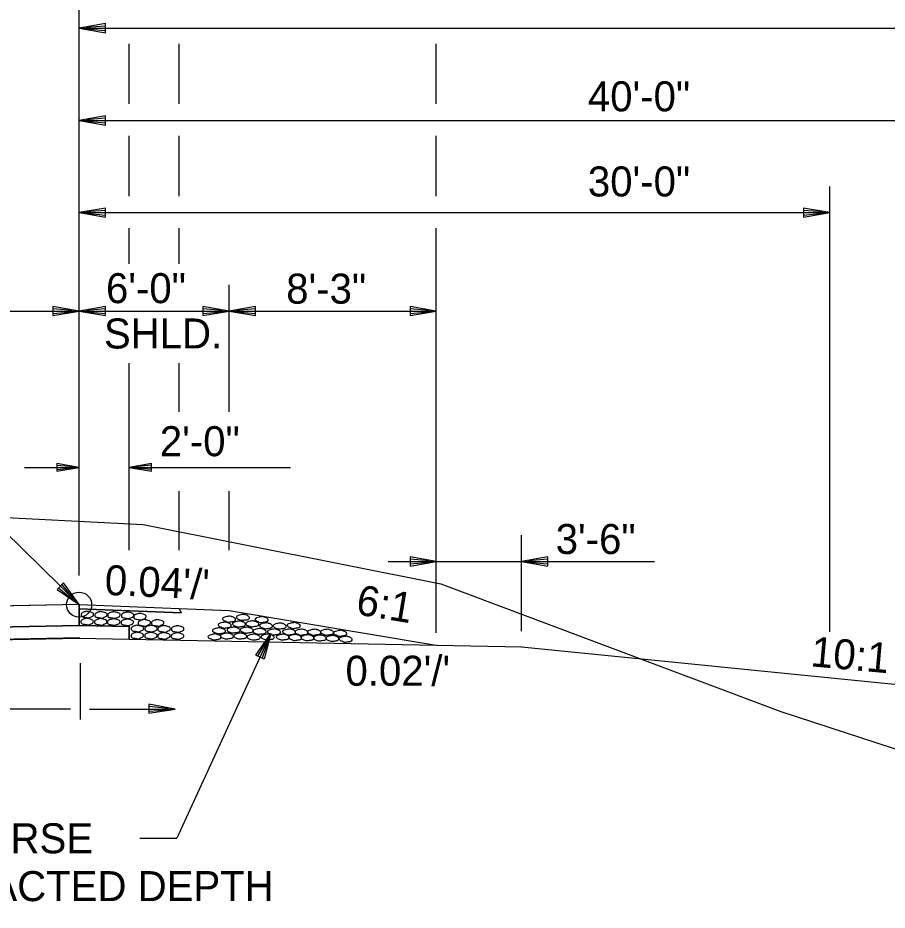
# Model space of a CAD drawing. Extents: x 1734743 to 1735935, y 759845 to 763831.
# Drawn here: x 1735710.69 to 1735745.44, y 760841.73 to 760877.4 of the extents above; entities that cross this region are included whole.
import ezdxf

# ---------------------------------------------------------------- set-up
doc = ezdxf.new("R2010")
doc.units = 0
for name, color, linetype in [('1', 7, 'Continuous'), ('19', 7, 'Continuous'), ('8', 7, 'Continuous'), ('Level 1', 7, 'Continuous'), ('R_Prop Surface', 7, 'Continuous')]:
    doc.layers.add(name, color=color, linetype=linetype)

# ---------------------------------------------------------------- blocks, each defined once
blk = doc.blocks.new('TM')
at = {"layer": '8'}
for p, q in [((-120.309, 21.181), (-119.787, -20.829)), ((0, 0), (-120.309, 21.181)), ((-31.382, 2.945), (-120.176, 10.512)), ((-119.787, -20.829), (0, 0)), ((-119.911, -10.826), (-31.307, -3.057))]:
    blk.add_line(p, q, dxfattribs=at)
blk = doc.blocks.new('ROCKS')
at = {"layer": '1'}
blk.add_spline([(0.013, 0.06), (0.053, 0.053), (0.107, 0.033), (0.133, 0.013), (0.133, -0.007), (0.12, -0.033), (0.107, -0.04), (0.073, -0.053), (0.033, -0.067), (0.013, -0.067), (-0.02, -0.06), (-0.06, -0.053), (-0.087, -0.047), (-0.113, -0.02), (-0.113, -0.007), (-0.107, 0.02), (-0.087, 0.033), (-0.067, 0.047), (-0.033, 0.053), (-0.02, 0.06), (0.013, 0.06)], degree=3, dxfattribs=at)

msp = doc.modelspace()

# ---------------------------------------------------------------- linework, layer by layer
at = {"layer": '19'}
for p, q in [((1735713.144, 760855.111), (1735713.144, 760877.958)), ((1735714.194, 760877.173), (1735713.144, 760876.99)), ((1735714.194, 760876.806), (1735714.194, 760877.173)), ((1735713.144, 760876.99), (1735793.144, 760876.99)), ((1735713.144, 760876.99), (1735714.194, 760876.806)), ((1735714.194, 760877.077), (1735713.424, 760877.016)), ((1735713.424, 760876.963), (1735714.194, 760876.893)), ((1735715.144, 760873.962), (1735715.144, 760876.371)), ((1735717.141, 760873.962), (1735717.141, 760876.371)), ((1735727.419, 760873.962), (1735727.419, 760876.371)), ((1735714.194, 760873.487), (1735713.144, 760873.303)), ((1735713.144, 760873.303), (1735753.144, 760873.303)), ((1735713.144, 760873.303), (1735714.194, 760873.119)), ((1735714.194, 760873.39), (1735713.424, 760873.329)), ((1735713.424, 760873.277), (1735714.194, 760873.207)), ((1735714.194, 760873.119), (1735714.194, 760873.487)), ((1735715.144, 760870.276), (1735715.144, 760872.684)), ((1735717.141, 760870.276), (1735717.141, 760872.684)), ((1735727.419, 760870.276), (1735727.419, 760872.684)), ((1735743.144, 760852.861), (1735743.144, 760870.662)), ((1735714.194, 760869.8), (1735713.144, 760869.616)), ((1735713.144, 760869.616), (1735714.194, 760869.432)), ((1735713.144, 760869.616), (1735743.144, 760869.616)), ((1735714.194, 760869.704), (1735713.424, 760869.642)), ((1735714.194, 760869.432), (1735714.194, 760869.8)), ((1735742.094, 760869.8), (1735742.094, 760869.433)), ((1735743.144, 760869.616), (1735742.094, 760869.8)), ((1735742.864, 760869.643), (1735742.094, 760869.704)), ((1735742.094, 760869.433), (1735743.144, 760869.616)), ((1735713.424, 760869.59), (1735714.194, 760869.52)), ((1735742.094, 760869.52), (1735742.864, 760869.59)), ((1735715.144, 760867.571), (1735715.144, 760868.998)), ((1735717.141, 760867.571), (1735717.141, 760868.998)), ((1735727.419, 760852.821), (1735727.419, 760868.998)), ((1735719.144, 760861.65), (1735719.144, 760866.731)), ((1735712.094, 760865.865), (1735712.094, 760865.497)), ((1735713.144, 760865.681), (1735712.094, 760865.865)), ((1735712.864, 760865.707), (1735712.094, 760865.768)), ((1735714.194, 760865.864), (1735713.144, 760865.681)), ((1735714.194, 760865.768), (1735713.424, 760865.707)), ((1735714.194, 760865.497), (1735714.194, 760865.864)), ((1735718.094, 760865.865), (1735718.094, 760865.497)), ((1735719.144, 760865.681), (1735718.094, 760865.865)), ((1735718.864, 760865.707), (1735718.094, 760865.768)), ((1735720.194, 760865.864), (1735719.144, 760865.681)), ((1735720.194, 760865.768), (1735719.424, 760865.707)), ((1735720.194, 760865.497), (1735720.194, 760865.864)), ((1735726.369, 760865.865), (1735726.369, 760865.497)), ((1735727.419, 760865.681), (1735726.369, 760865.865)), ((1735727.139, 760865.707), (1735726.369, 760865.768)), ((1735701.144, 760865.681), (1735713.144, 760865.681)), ((1735712.094, 760865.497), (1735713.144, 760865.681)), ((1735712.094, 760865.585), (1735712.864, 760865.655)), ((1735713.144, 760865.681), (1735719.144, 760865.681)), ((1735713.144, 760865.681), (1735714.194, 760865.497)), ((1735713.424, 760865.654), (1735714.194, 760865.584)), ((1735718.094, 760865.497), (1735719.144, 760865.681)), ((1735718.094, 760865.585), (1735718.864, 760865.655)), ((1735719.144, 760865.681), (1735727.419, 760865.681)), ((1735719.144, 760865.681), (1735720.194, 760865.497)), ((1735719.424, 760865.654), (1735720.194, 760865.584)), ((1735726.369, 760865.497), (1735727.419, 760865.681)), ((1735726.369, 760865.585), (1735727.139, 760865.655)), ((1735743.144, 760853.272), (1735743.144, 760864.185)), ((1735715.144, 760858.482), (1735715.144, 760863.602)), ((1735717.141, 760861.65), (1735717.141, 760863.602)), ((1735713.144, 760857.532), (1735713.144, 760861.396)), ((1735715.144, 760856.115), (1735715.144, 760861.379)), ((1735710.955, 760859.432), (1735713.144, 760859.432)), ((1735712.25, 760859.589), (1735712.25, 760859.276)), ((1735713.144, 760859.432), (1735712.25, 760859.589)), ((1735712.906, 760859.454), (1735712.25, 760859.507)), ((1735712.25, 760859.276), (1735713.144, 760859.432)), ((1735712.25, 760859.35), (1735712.906, 760859.41)), ((1735716.038, 760859.59), (1735715.144, 760859.433)), ((1735715.144, 760859.433), (1735716.038, 760859.277)), ((1735715.144, 760859.433), (1735721.592, 760859.429)), ((1735716.038, 760859.515), (1735715.382, 760859.456)), ((1735715.382, 760859.411), (1735716.038, 760859.359)), ((1735716.038, 760859.277), (1735716.038, 760859.59)), ((1735715.144, 760856.115), (1735715.144, 760858.482)), ((1735717.141, 760856.115), (1735717.141, 760858.482)), ((1735719.144, 760856.115), (1735719.144, 760858.482)), ((1735727.419, 760852.888), (1735727.419, 760857.451)), ((1735730.828, 760852.888), (1735730.828, 760856.721)), ((1735726.369, 760855.855), (1735726.369, 760855.487)), ((1735727.419, 760855.671), (1735726.369, 760855.855)), ((1735727.139, 760855.697), (1735726.369, 760855.759)), ((1735731.878, 760855.855), (1735730.828, 760855.671)), ((1735731.878, 760855.758), (1735731.108, 760855.697)), ((1735731.878, 760855.487), (1735731.878, 760855.855)), ((1735725.491, 760855.671), (1735736.138, 760855.671)), ((1735726.369, 760855.487), (1735727.419, 760855.671)), ((1735726.369, 760855.575), (1735727.139, 760855.645)), ((1735730.828, 760855.671), (1735731.878, 760855.487)), ((1735731.108, 760855.645), (1735731.878, 760855.575)), ((1735712.523, 760854.809), (1735712.269, 760854.546)), ((1735712.96, 760854.153), (1735712.462, 760854.739)), ((1735713.144, 760853.943), (1735712.523, 760854.809)), ((1735712.269, 760854.546), (1735713.144, 760853.943)), ((1735712.33, 760854.608), (1735712.925, 760854.118)), ((1735713.144, 760853.943), (1735687.144, 760853.423)), ((1735713.144, 760853.943), (1735719.144, 760853.703)), ((1735713.144, 760853.943), (1735713.144, 760853.109)), ((1735713.144, 760853.776), (1735717.226, 760853.613)), ((1735719.144, 760853.703), (1735727.419, 760852.324)), ((1735713.144, 760853.109), (1735687.144, 760852.589)), ((1735713.144, 760853.109), (1735687.144, 760852.589)), ((1735713.144, 760853.109), (1735687.144, 760852.589)), ((1735713.144, 760853.109), (1735715.144, 760853.069)), ((1735713.144, 760853.109), (1735715.144, 760853.069)), ((1735715.144, 760853.069), (1735715.144, 760852.569)), ((1735713.174, 760852.61), (1735685.18, 760852.05)), ((1735713.144, 760852.609), (1735715.144, 760852.569)), ((1735715.144, 760852.569), (1735730.835, 760852.255)), ((1735720.81, 760852.794), (1735717.047, 760844.602)), ((1735720.207, 760851.919), (1735720.81, 760852.794)), ((1735720.286, 760851.884), (1735720.668, 760852.553)), ((1735720.713, 760852.533), (1735720.456, 760851.808)), ((1735720.81, 760852.794), (1735720.538, 760851.764)), ((1735730.82, 760852.257), (1735753.147, 760850.024)), ((1735730.82, 760852.257), (1735753.147, 760850.024)), ((1735720.538, 760851.764), (1735720.207, 760851.919)), ((1735713.181, 760851.607), (1735713.181, 760849.354)), ((1735712.802, 760849.77), (1735709.381, 760849.77)), ((1735713.56, 760849.77), (1735716.981, 760849.77)), ((1735715.573, 760844.602), (1735717.047, 760844.602))]:
    msp.add_line(p, q, dxfattribs=at)
for points in [[(1735706.762, 760859.123), (1735707.866, 760859.123), (1735713.144, 760853.943)], [(1735708.913, 760857.494), (1735715.706, 760857.154), (1735727.595, 760854.774), (1735741.182, 760849.673), (1735752.088, 760846.116)], [(1735717.226, 760853.613), (1735713.144, 760853.776), (1735713.144, 760853.776), (1735713.144, 760853.943), (1735713.144, 760853.943), (1735713.144, 760853.943), (1735717.141, 760853.783), (1735717.141, 760853.783), (1735717.141, 760853.783), (1735717.226, 760853.613), (1735717.226, 760853.613), (1735717.226, 760853.613)]]:
    msp.add_lwpolyline(points, dxfattribs=at)
for points in [[(1735713.144, 760853.943), (1735687.144, 760853.423), (1735687.144, 760852.589), (1735713.144, 760853.109)], [(1735715.144, 760853.069), (1735713.144, 760853.109), (1735713.144, 760853.109), (1735685.145, 760852.549), (1735685.145, 760852.049), (1735685.145, 760852.049), (1735713.144, 760852.609), (1735715.144, 760852.569)]]:
    msp.add_lwpolyline(points, close=True, dxfattribs=at)
msp.add_circle((1735713.144, 760853.943), 0.5, dxfattribs=at)
at = {"layer": 'R_Prop Surface'}
msp.add_line((1735717.141, 760853.783), (1735717.226, 760853.613), dxfattribs=at)

# ---------------------------------------------------------------- block references
at = {"layer": '19', "xscale": 0.008761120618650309, "yscale": 0.008761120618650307, "rotation": -0.7994241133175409}
msp.add_blockref('TM', (1735716.981, 760849.766), dxfattribs=at)
at = {"layer": 'Level 1'}
for p, xscale, yscale, rotation in [((1735713.453, 760853.552), 2.011654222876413, 2.011654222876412, 0.7559682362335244), ((1735713.997, 760853.541), 2.011654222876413, 2.011654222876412, 0.7559682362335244), ((1735714.518, 760853.532), 2.011654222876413, 2.011654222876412, 0.7559682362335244), ((1735715.061, 760853.521), 2.011654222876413, 2.011654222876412, 0.7559682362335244), ((1735715.552, 760853.469), 2.0116542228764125, 2.011654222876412, 1.1160463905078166), ((1735719.71, 760853.44), 2.011654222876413, -2.011654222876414, 178.00441377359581), ((1735713.443, 760853.272), 2.011654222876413, 2.011654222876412, 0.7559682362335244), ((1735713.986, 760853.262), 2.011654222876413, 2.011654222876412, 0.7559682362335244), ((1735714.508, 760853.252), 2.011654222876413, 2.011654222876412, 0.7559682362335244), ((1735715.05, 760853.242), 2.011654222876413, 2.011654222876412, 0.7559682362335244), ((1735715.729, 760853.222), 2.0116542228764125, 2.011654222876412, 1.1160463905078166), ((1735716.262, 760853.22), 2.0116542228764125, 2.011654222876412, 1.1160463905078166), ((1735716.262, 760853.22), 2.0116542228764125, 2.011654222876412, 1.1160463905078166), ((1735718.984, 760853.129), 2.011654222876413, -2.011654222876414, 178.00441377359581), ((1735719.158, 760853.368), 2.011654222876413, -2.011654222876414, 178.00441377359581), ((1735719.559, 760853.174), 2.011654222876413, -2.011654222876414, 178.00441377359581), ((1735720.081, 760853.182), 2.011654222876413, -2.011654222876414, 178.00441377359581), ((1735720.457, 760853.351), 2.011654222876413, -2.011654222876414, 178.00441377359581), ((1735720.635, 760853.103), 2.011654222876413, -2.011654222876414, 178.00441377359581), ((1735721.182, 760853.093), 2.011654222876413, -2.011654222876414, 178.00441377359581), ((1735721.742, 760853.114), 2.011654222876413, -2.011654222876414, 178.00441377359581), ((1735715.446, 760852.714), 2.0116542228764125, 2.011654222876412, 1.1160463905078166), ((1735715.455, 760852.994), 2.0116542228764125, 2.011654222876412, 1.1160463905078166), ((1735715.99, 760852.708), 2.0116542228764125, 2.011654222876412, 1.1160463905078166), ((1735715.998, 760852.988), 2.0116542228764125, 2.011654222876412, 1.1160463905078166), ((1735716.52, 760852.981), 2.0116542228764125, 2.011654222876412, 1.1160463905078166), ((1735717.063, 760852.974), 2.0116542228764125, 2.011654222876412, 1.1160463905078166), ((1735718.752, 760852.904), 2.011654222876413, -2.011654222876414, 178.00441377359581), ((1735719.335, 760852.932), 2.011654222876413, -2.011654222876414, 178.00441377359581), ((1735719.861, 760852.929), 2.011654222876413, -2.011654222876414, 178.00441377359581), ((1735720.376, 760852.879), 2.011654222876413, -2.011654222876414, 178.00441377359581), ((1735720.949, 760852.858), 2.011654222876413, -2.011654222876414, 178.00441377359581), ((1735721.557, 760852.857), 2.011654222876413, -2.011654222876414, 178.00441377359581), ((1735722.05, 760852.849), 2.011654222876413, -2.011654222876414, 178.00441377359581), ((1735722.56, 760852.847), 2.011654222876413, -2.011654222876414, 178.00441377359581), ((1735723.072, 760852.846), 2.011654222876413, -2.011654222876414, 178.00441377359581), ((1735723.597, 760852.805), 2.011654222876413, -2.011654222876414, 178.00441377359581), ((1735716.511, 760852.701), 2.0116542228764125, 2.011654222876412, 1.1160463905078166), ((1735717.054, 760852.694), 2.0116542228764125, 2.011654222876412, 1.1160463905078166), ((1735718.575, 760852.658), 2.011654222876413, -2.011654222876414, 178.00441377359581), ((1735719.071, 760852.694), 2.011654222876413, -2.011654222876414, 178.00441377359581), ((1735719.603, 760852.693), 2.011654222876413, -2.011654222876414, 178.00441377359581), ((1735720.137, 760852.651), 2.011654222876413, -2.011654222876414, 178.00441377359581), ((1735720.697, 760852.654), 2.011654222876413, -2.011654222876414, 178.00441377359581), ((1735721.305, 760852.652), 2.011654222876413, -2.011654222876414, 178.00441377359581), ((1735721.795, 760852.635), 2.011654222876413, -2.011654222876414, 178.00441377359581), ((1735722.292, 760852.626), 2.011654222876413, -2.011654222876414, 178.00441377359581), ((1735722.787, 760852.614), 2.011654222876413, -2.011654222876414, 178.00441377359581), ((1735723.287, 760852.598), 2.011654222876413, -2.011654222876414, 178.00441377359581), ((1735723.816, 760852.567), 2.011654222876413, -2.011654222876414, 178.00441377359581)]:
    msp.add_blockref('ROCKS', p, dxfattribs=dict(at, xscale=xscale, yscale=yscale, rotation=rotation))

# ---------------------------------------------------------------- texts
at = {"layer": '19'}
for s, p in [('40\'-0"', (1735733.476, 760873.667)), ('30\'-0"', (1735733.476, 760870.263)), ('6\'-0"', (1735714.217, 760865.997)), ('8\'-3"', (1735721.42, 760865.977)), ('SHLD.', (1735714.136, 760864.185)), ('2\'-0"', (1735716.369, 760859.878)), ('3\'-6"', (1735732.19, 760855.968)), ("0.02'/'", (1735723.789, 760850.7))]:
    msp.add_text(s, height=1.2, dxfattribs=at).set_placement(p)
for s, rotation, p in [("0.04'/'", 357.3887, (1735714.149, 760854.335)), ('6:1', 350.5489, (1735724.166, 760853.565)), ('10:1', 354.8422, (1735742.351, 760851.481)), ('AGGREGATE BASE COURSE', 360, (1735691.498, 760844.002)), ('(CLASS 7) - VAR. COMPACTED DEPTH', 360, (1735691.498, 760842.09))]:
    msp.add_text(s, height=1.2, rotation=rotation, dxfattribs=at).set_placement(p)

doc.saveas('drawing.dxf')
